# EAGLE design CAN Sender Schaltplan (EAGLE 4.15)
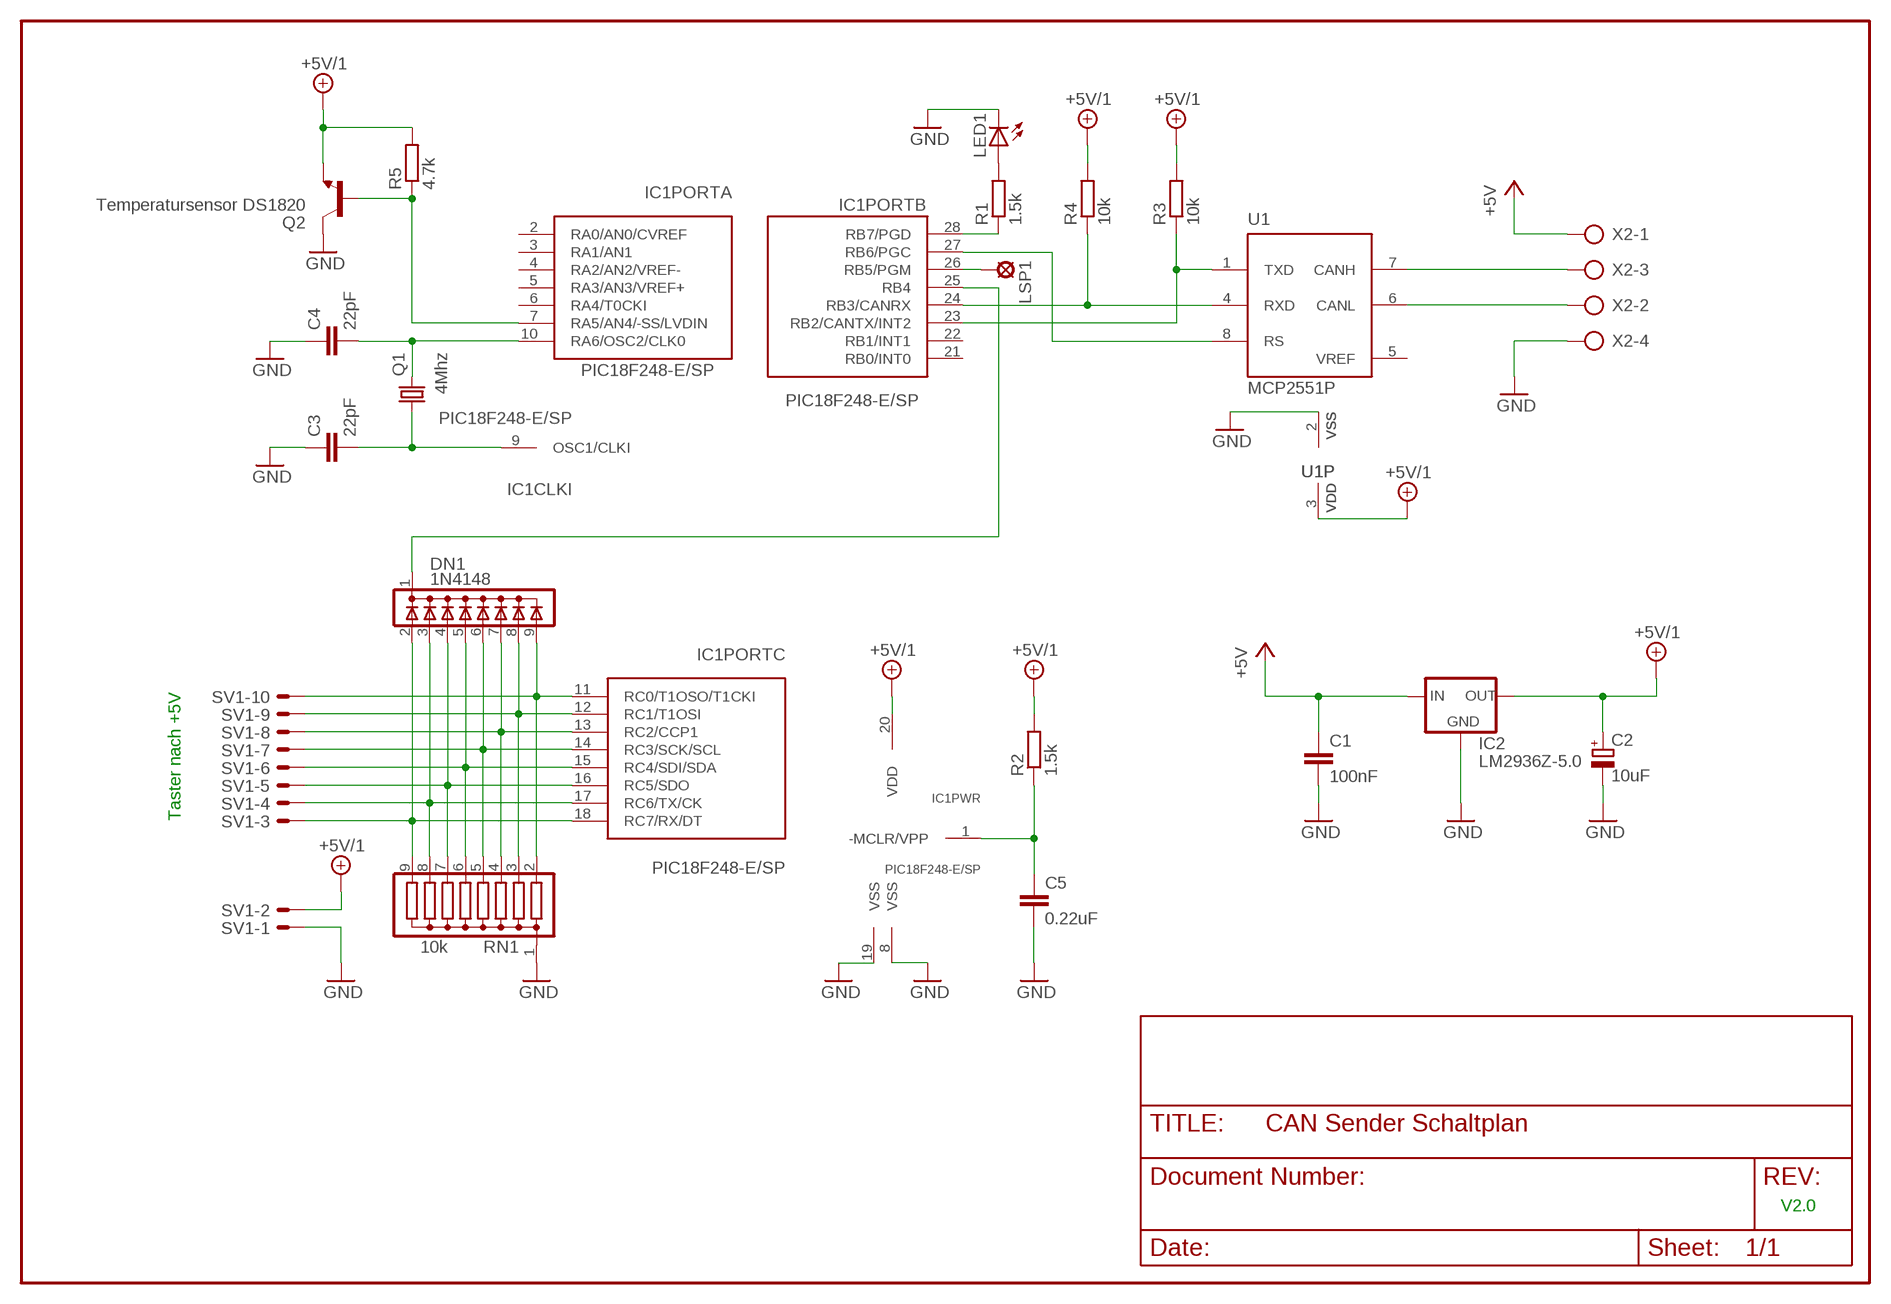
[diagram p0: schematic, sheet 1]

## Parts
C1  100nF  C2.5/2  [C2.5-2]
C2  10uF  CPOL-EUB45181A  [B45181A]
C3  22pF  C-EU025-025X050  [C025-025X050]
C4  22pF  C-EU025-025X050  [C025-025X050]
C5  0.22uF  C-EU025-025X050  [C025-025X050]
DN1  1N4148  D9-1C  [SIL09C]
IC1  PIC18F248-E/SP  [DIL28-3]
IC2  LM2936Z-5.0  78LXX  [78LXX]
LED1  LED3MM  [LED3MM]
LSP1  LSP10  [LSP10]
Q1  4Mhz  CRYTALHC49S  [HC49/S]
Q2  Temperatursensor DS1820  BC238  [TO92]
R1  1.5k  R-EU_0207/2V  [0207/2V]
R2  1.5k  R-EU_0207/2V  [0207/2V]
R3  10k  R-EU_0207/2V  [0207/2V]
R4  10k  R-EU_0207/2V  [0207/2V]
R5  4.7k  R-EU_0207/2V  [0207/2V]
RN1  10k  G08R  [SIL9]
SV1  ML10E  [ML10]
U1  MCP2551P  [DIL8]
X2  AK500/4  [AK500/4]

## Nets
+5V: C1.1 IC2.IN X2.1
+5V/1: C2.+ IC1.20(PWR:VDD) IC2.OUT Q2.1(E) R2.2 R3.2 R4.2 R5.2 SV1.2 U1.3(VDD)
GND: C1.2 C2.- C3.1 C4.1 C5.2 IC1.8(PWR:VSS) IC1.19(PWR:VSS) IC2.GND LED1.K(C) Q2.3(C) RN1.1 SV1.1 U1.2(VSS) X2.4
N$1: IC1.23(PORTB:RB2/CANTX/INT2) R3.1 U1.1(TXD)
N$2: IC1.24(PORTB:RB3/CANRX) R4.1 U1.4(RXD)
N$3: U1.7(CANH) X2.3
N$4: C3.2 IC1.9(CLKI:OSC1/CLKI) Q1.1
N$5: U1.6(CANL) X2.2
N$6: DN1.1(C) IC1.25(PORTB:RB4)
N$7: DN1.9 IC1.11(PORTC:RC0/T1OSO/T1CKI) RN1.2 SV1.10
N$8: DN1.8 IC1.12(PORTC:RC1/T1OSI) RN1.3 SV1.9
N$9: C4.2 IC1.10(PORTA:RA6/OSC2/CLK0) Q1.2
N$10: LED1.A R1.2
N$11: IC1.28(PORTB:RB7/PGD) R1.1
N$12: DN1.7 IC1.13(PORTC:RC2/CCP1) RN1.4 SV1.8
N$13: DN1.6 IC1.14(PORTC:RC3/SCK/SCL) RN1.5 SV1.7
N$14: C5.1 IC1.1(PWR:-MCLR/VPP) R2.1
N$15: DN1.2 IC1.18(PORTC:RC7/RX/DT) RN1.9 SV1.3
N$16: DN1.4 IC1.16(PORTC:RC5/SDO) RN1.7 SV1.5
N$17: DN1.3 IC1.17(PORTC:RC6/TX/CK) RN1.8 SV1.4
N$18: IC1.27(PORTB:RB6/PGC) U1.8(RS)
N$19: IC1.7(PORTA:RA5/AN4/-SS/LVDIN) Q2.2(B) R5.1
N$20: IC1.26(PORTB:RB5/PGM) LSP1.MP
N$21: DN1.5 IC1.15(PORTC:RC4/SDI/SDA) RN1.6 SV1.6
Unconnected: IC1.2(PORTA:RA0/AN0/CVREF) IC1.3(PORTA:RA1/AN1) IC1.4(PORTA:RA2/AN2/VREF-) IC1.5(PORTA:RA3/AN3/VREF+) IC1.6(PORTA:RA4/T0CKI) IC1.21(PORTB:RB0/INT0) IC1.22(PORTB:RB1/INT1)

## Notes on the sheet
- Taster nach +5V
- V2.0

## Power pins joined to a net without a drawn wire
VREF: U1.5(VREF)

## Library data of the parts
C1 = capacitor-wima:C: CAPACITOR
C2 = rcl:CPOL-EU: POLARIZED CAPACITOR, European symbol
C3-C5 = rcl:C-EU: CAPACITOR, European symbol
DN1 = diode:D9-1C: 8 DIODES SIL, common cathode
IC1 = pic18fxx20-fxx8:PIC18F2*8: 28-Pin High Performance, Enhanced FLASH Microcontrollers with CAN device program memory (bytes) data RAM (bytes) PIC18F24816K768 PIC18F25832K1536
IC2 = v-reg:78LXX: VOLTAGE REGULATOR
LED1 = led:LED: LED
LSP1 = solpad:LSP10: SOLDER PAD
Q1 = crystal:CRYTAL: CRYSTAL
Q2 = transistor-npn:BC238: NPN Transistor
R1-R5 = rcl:R-EU_: RESISTOR, European symbol
RN1 = resistor-sil:G08R: SIL RESISTOR
SV1 = con-harting-ml:ML10?E: HARTING
U1 = microchip_can:MCP2551: High Speed CAN tranceiver
X2 = con-ptr500:AK500/4: CONNECTOR

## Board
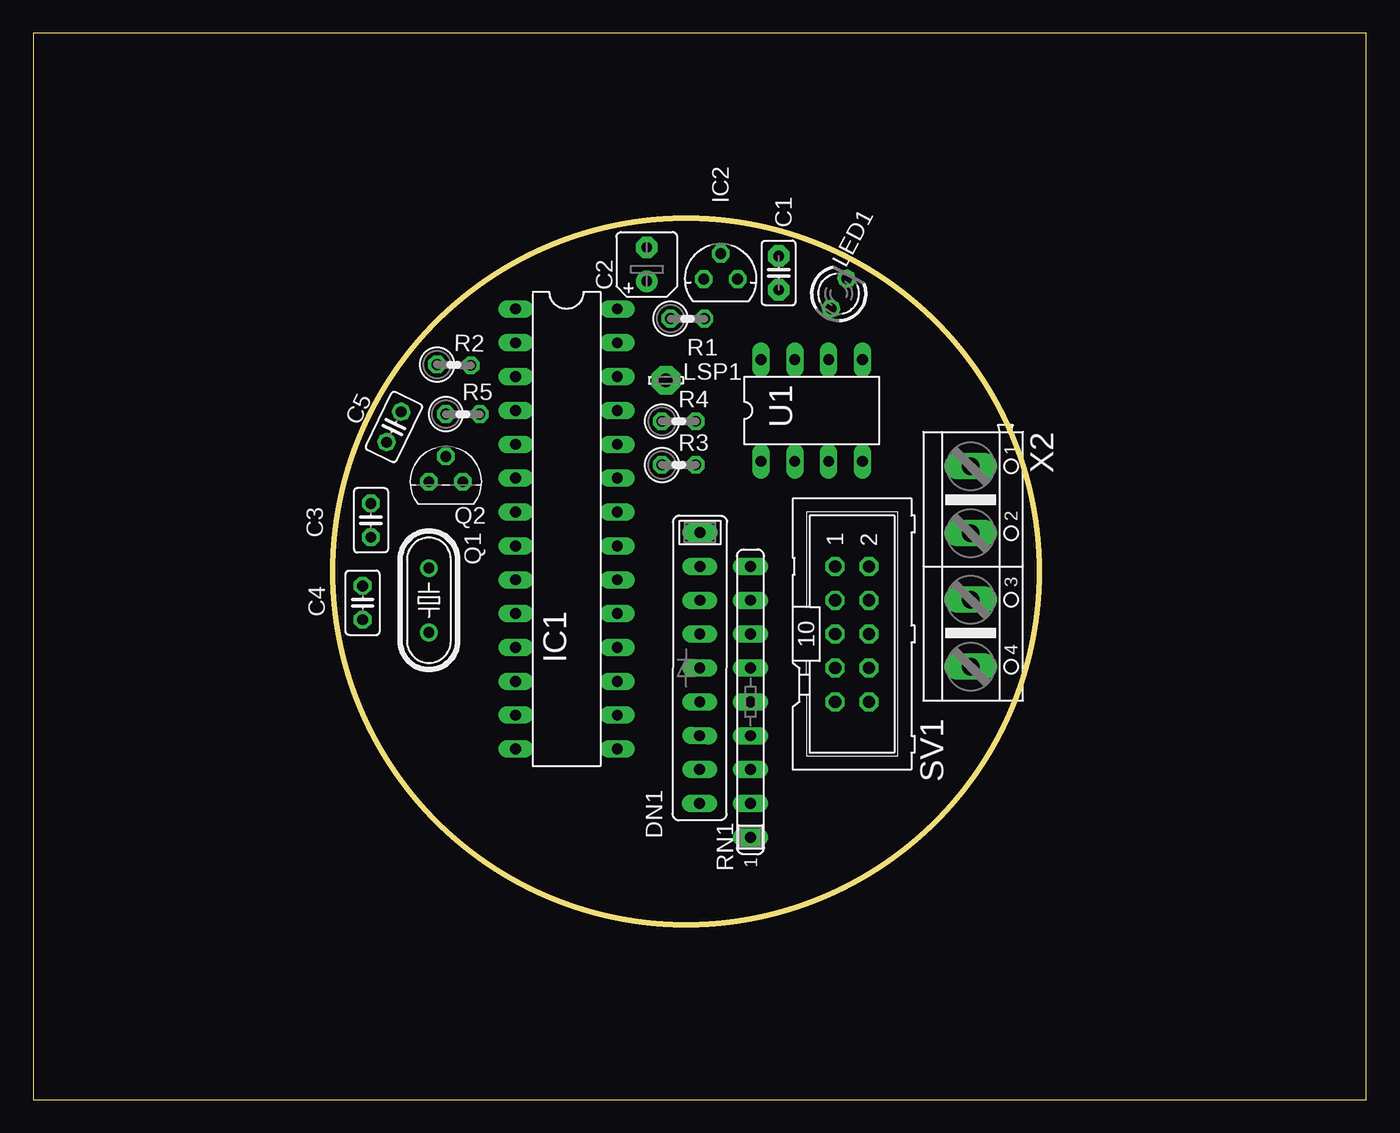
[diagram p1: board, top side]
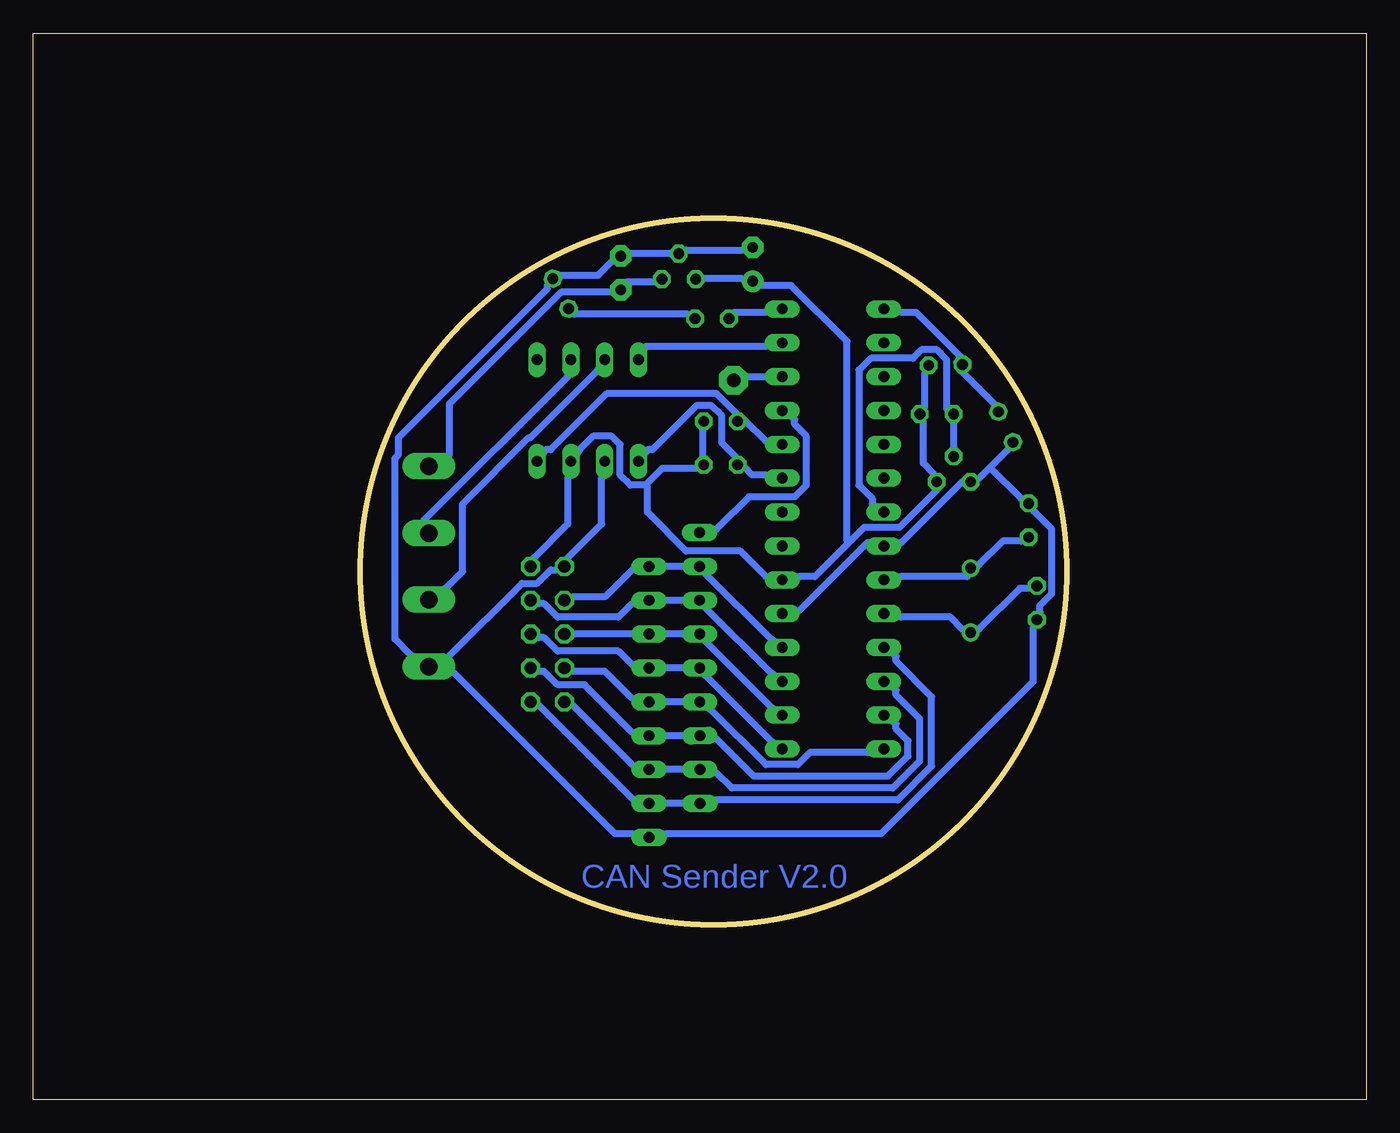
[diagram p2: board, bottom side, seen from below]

Size 100 x 80 mm. Coordinates in mm from the lower left corner, seen from the top.
Outline: 0,0 100,0 100,80 0,80 0,0
Outline: circle at 48.97,39.63 radius 26.5
Copper layers (1*16): Top 0.035mm / dielectric 1.5mm / Bottom 0.035mm
Design rules "default": minimum track width 20mil, minimum drill 24mil, track to track 15mil, track to pad 8mil, pad to pad 8mil, via to via 8mil, smd to smd 8mil, copper to edge 10mil, drill to drill 8mil, minimum pad ring 10mil, minimum via ring 8mil, stop-mask expansion 4mil, vias tented up to drill 0mil, thermal gap 10mil

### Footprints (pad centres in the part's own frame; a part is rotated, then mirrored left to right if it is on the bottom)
C2.5-2 = drill 0.813 pad 1.6 octagon: 1 -1.27,0; 2 1.27,0
B45181A = drill 0.813 pad 1.6 round: + -1.27,0 | drill 0.813 pad 1.6 octagon: - 1.27,0
C025-025X050 = drill 0.813 octagon: 1 -1.27,0; 2 1.27,0
SIL09C = drill 0.813 long: 1 -10.16,0; 2 -7.62,0; 3 -5.08,0; 4 -2.54,0; 5 0,0; 6 2.54,0; 7 5.08,0; 8 7.62,0; 9 10.16,0
DIL28-3 = drill 0.813 long: 1 -16.51,-3.81; 2 -13.97,-3.81; 3 -11.43,-3.81; 4 -8.89,-3.81; 5 -6.35,-3.81; 6 -3.81,-3.81; 7 -1.27,-3.81; 8 1.27,-3.81; 9 3.81,-3.81; 10 6.35,-3.81; 11 8.89,-3.81; 12 11.43,-3.81; 13 13.97,-3.81; 14 16.51,-3.81; 15 16.51,3.81; 16 13.97,3.81; 17 11.43,3.81; 18 8.89,3.81; 19 6.35,3.81; 20 3.81,3.81; 21 1.27,3.81; 22 -1.27,3.81; 23 -3.81,3.81; 24 -6.35,3.81; 25 -8.89,3.81; 26 -11.43,3.81; 27 -13.97,3.81; 28 -16.51,3.81
78LXX = drill 0.813 octagon: GND 0,1.905; IN 1.27,0; OUT -1.27,0
LED3MM = drill 0.813 octagon: A -1.27,0; K 1.27,0
LSP10 = drill 1.016 pad 2.159 octagon: MP 0,0
HC49/S = drill 0.813 round: 1 -2.413,0; 2 2.413,0
TO92 = drill 0.813 octagon: 1 1.27,0; 2 0,1.905; 3 -1.27,0
0207/2V = drill 0.813 octagon: 1 -1.27,0; 2 1.27,0
SIL9 = drill 0.813 long: 1 -10.16,0; 2 -7.62,0; 3 -5.08,0; 4 -2.54,0; 5 0,0; 6 2.54,0; 7 5.08,0; 8 7.62,0; 9 10.16,0
ML10 = drill 0.914 octagon: 1 -5.08,-1.27; 2 -5.08,1.27; 3 -2.54,-1.27; 4 -2.54,1.27; 5 0,-1.27; 6 0,1.27; 7 2.54,-1.27; 8 2.54,1.27; 9 5.08,-1.27; 10 5.08,1.27
DIL8 = drill 0.813 long: 1 -3.81,-3.81; 2 -1.27,-3.81; 3 1.27,-3.81; 4 3.81,-3.81; 5 3.81,3.81; 6 1.27,3.81; 7 -1.27,3.81; 8 -3.81,3.81
AK500/4 = drill 1.321 long: 1 -7.518,0; 2 -2.489,0; 3 2.489,0; 4 7.518,0

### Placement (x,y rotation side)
C1  55.92,62.02 90 top
C2  46.03,62.67 90 top
C3  25.33,43.46 270 top
C4  24.71,37.27 90 top
C5  27.05,50.46 244.2 top
DN1  50,32.38 269.9 top
IC1  40,42.81 270 top
IC2  51.57,61.56 0 top
LED1  60.43,60.47 62.2 top
LSP1  47.46,53.97 0 top
Q1  29.68,37.46 270 top
Q2  30.95,46.35 0 top
R1  49.08,58.59 0 top
R2  31.56,55.12 358.5 top
R3  48.43,47.62 0 top
R4  48.43,50.89 0 top
R5  32.22,51.43 0 top
RN1  53.81,29.84 90 top
SV1  61.43,34.92 270 top
U1  58.4,51.7 0 top
X2  70.32,40 270 top

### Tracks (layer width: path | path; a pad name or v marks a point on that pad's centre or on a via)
+5V
  Bottom 0.508: IC2.IN 53.43,61.34 55.46,61.34 C1.1 56.6,60.57 60.41,60.57 68.8,52.19 68.8,48.38 X2.1
+5V/1
  Bottom 0.508: R4.2 49.75,50.29 49.75,48.26 R3.2 50.25,47.37 52.79,47.37 54.06,46.1 | SV1.2 62.45,40.64 59.91,43.18 59.91,46.6 U1.3 59.02,48.76 58,49.78 56.6,49.78 55.97,49.14 55.97,46.86 55.21,46.1 54.06,46.1 | IC2.OUT 49.75,61.59 46.82,61.59 C2.+ 45.3,61.08 43.14,61.08 38.95,56.89 38.95,41.91 38.82,41.78 | R2.2 33.11,54.48 33.11,51.94 R5.2 33.24,50.8 33.24,47.75 32.47,46.98 Q2.1 32.22,45.72 35.01,42.92 37.68,42.92 38.82,41.78 | 38.82,41.78 41.36,39.24 42.51,39.24 IC1.20 45.05,39.24 46.95,41.14 51.02,41.14 53.94,44.06 53.94,45.97 54.06,46.1
GND
  Bottom 0.508: 28.22,47.43 26.89,48.76 C5.2 | 28.22,47.43 29.04,46.6 Q2.3 30.31,46.35 34.89,41.78 IC1.8 37.43,41.78 42.51,36.7 IC1.19 | 28.22,47.43 25.87,45.08 C3.1 24.98,44.19 23.58,42.79 23.58,37.97 24.47,37.08 24.47,36.57 C4.1 24.98,35.43 24.98,31.36 36.41,19.93 52.54,19.93 RN1.1 55.08,19.93 56.35,19.93 68.41,32 X2.4 | C2.- 46.82,63.75 51.02,63.75 IC2.GND 52.16,63.5 55.21,63.5 C1.2 56.6,62.86 57.62,61.84 60.41,61.84 LED1.K 61.43,61.08 61.43,60.83 72.61,49.65 72.61,48.38 72.86,48.13 72.86,34.54 71.72,33.4 X2.4 | U1.2 57.37,46.6 57.37,43.18 59.91,40.64 SV1.1 60.8,39.75 61.18,39.75 62.19,38.73 63.34,38.73 68.8,33.27 X2.4
N$1
  Bottom 0.508: IC1.23 45.05,46.86 46.06,46.86 46.57,47.37 R3.1 47.33,48.26 48.35,49.27 48.35,51.3 49.11,52.07 50.25,52.07 53.56,48.76 53.94,48.76 U1.1
N$2
  Bottom 0.508: IC1.24 45.05,49.4 46.57,50.92 R4.1 47.21,51.43 48.73,52.95 56.98,52.95 61.18,48.76 61.56,48.76 U1.4
N$3
  Bottom 0.508: U1.7 57.75,54.61 62.7,49.65 62.83,49.65 67.78,44.7 67.78,39.62 68.92,38.48 X2.3
N$4
  Bottom 0.508: C3.2 25.87,41.91 27.27,41.91 29.04,40.13 Q1.1 29.93,39.24 34.89,39.24 IC1.9
N$5
  Bottom 0.508: U1.6 59.91,54.22 70.7,43.43 X2.2
N$6
  Bottom 0.508: IC1.25 42.89,51.05 42.89,50.67 42,49.78 42,46.1 42.89,45.21 46.32,45.21 48.73,42.79 DN1.1
N$7
  Bottom 0.508: IC1.11 35.27,33.27 35.27,32.89 32.6,30.22 32.6,25.01 35.14,22.47 48.73,22.47 DN1.9 RN1.2 54.95,22.47 62.06,29.59 SV1.10
N$8
  Bottom 0.508: IC1.12 35.27,30.73 35.27,30.35 33.49,28.57 33.49,25.39 35.52,23.36 47.59,23.36 48.73,24.51 DN1.8 RN1.3 54.95,25.01 59.52,29.59 SV1.9
N$9
  Bottom 0.508: C4.2 25.36,38.35 26,38.35 29.04,35.3 Q1.2 30.31,35.3 31.2,36.19 34.89,36.19 IC1.10
N$10
  Bottom 0.508: R1.2 50.89,58.92 59.4,58.92 LED1.A
N$11
  Bottom 0.508: IC1.28 45.05,59.05 47.46,59.05 R1.1
N$12
  Bottom 0.508: IC1.13 35.27,28.19 35.27,27.81 34.38,26.92 34.38,25.78 35.9,24.25 45.94,24.25 48.73,27.05 DN1.7 RN1.4 55.08,27.55 58.64,31.11 60.67,31.11 61.68,32.13 62.06,32.13 SV1.8
N$13
  Bottom 0.508: IC1.14 37.43,26.03 41.74,26.03 42.63,25.14 45.05,25.14 49.11,29.2 DN1.6 RN1.5 55.08,30.09 57.11,32.13 59.52,32.13 SV1.7
N$14
  Bottom 0.508: C5.1 27.9,52.19 30.31,54.61 R2.1 30.44,55.75 33.74,59.05 34.89,59.05 IC1.1
N$15
  Bottom 0.508: IC1.18 44.67,34.54 49.49,39.37 DN1.2 51.27,40 RN1.9 55.08,39.75 57.11,37.71 59.52,37.71 SV1.3
N$16
  Bottom 0.508: IC1.16 44.67,29.46 49.49,34.29 DN1.4 51.27,34.92 RN1.7 SV1.5
N$17
  Bottom 0.508: IC1.17 44.67,32 49.49,36.83 DN1.3 51.27,37.46 RN1.8 55.08,37.21 56.1,36.19 60.67,36.19 61.68,37.21 62.06,37.21 SV1.4
N$18
  Bottom 0.508: IC1.27 45.05,56.51 54.06,56.51 U1.8
N$19
  Bottom 0.508: Q2.2 R5.1 31.46,51.81 31.46,55.49 32.22,56.26 33.36,56.26 34,55.62 37.17,55.62 38.06,54.73 38.06,46.1 37.05,45.08 37.05,44.7 IC1.7
N$20
  Bottom 0.508: IC1.26 45.05,54.22 46.44,54.22 LSP1.MP
N$21
  Bottom 0.508: IC1.15 44.67,26.92 49.49,31.74 DN1.5 RN1.6 55.08,32.63 56.1,33.65 60.67,33.65 61.68,34.67 62.06,34.67 SV1.6

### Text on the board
Bottom: CAN Sender V2.0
